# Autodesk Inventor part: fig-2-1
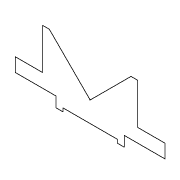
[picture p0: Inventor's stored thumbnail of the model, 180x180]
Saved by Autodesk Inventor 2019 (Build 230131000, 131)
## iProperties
Created: 2011-06
Part Number: fig-2-1
Material: Generic
Document SubType Name: Modeling
Designer: CadCim
Density: 1 g/cm^3
Appearance: Default
Author: CadCim
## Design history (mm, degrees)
sketch "Sketch1"
  geometry: L1 (2, -1.75)-(2.5, -1.75); L2 (-2.5, -1.75)-(-2, -1.75); L3 (-2, -1.75)-(-2, -2); L4 (-2.5, -2.5)-(-2.5, -1.75); L5 (-3, -6.5)-(-3.5, -6.5); L6 (-3.5, -6.5)-(-3.5, -3.5); L7 (-5.5, -2.5)-(-2.5, -2.5); L8 (-5.5, -3.5)-(-5.5, -2.5); L9 (-3.5, -3.5)-(-5.5, -3.5); L10 (0, -3.5)-(-3, -6.5); L11 (-2, -2)-(2, -2); L12 (3, -6.5)-(0, -3.5); L13 (2, -2)-(2, -1.75); L14 (2.5, -1.75)-(2.5, -2.5); L15 (3.5, -6.5)-(3, -6.5); L16 (3.5, -3.5)-(3.5, -6.5); L17 (5.5, -3.5)-(3.5, -3.5); L18 (2.5, -2.5)-(5.5, -2.5); L19 (5.5, -2.5)-(5.5, -3.5); 1 further point
  constraints: 38 end point
